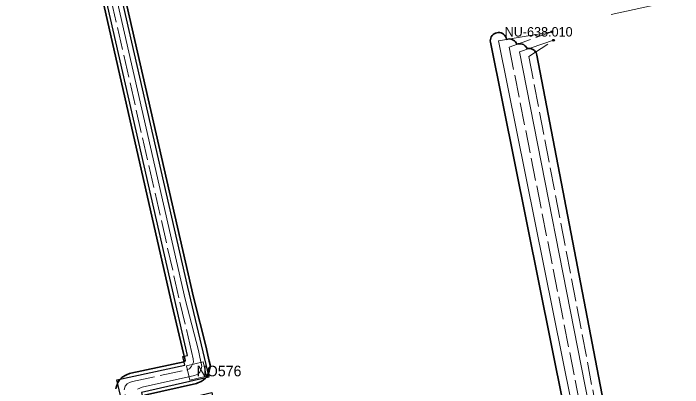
# Model space of a CAD drawing. Extents: x -452602 to -451136, y -1100088 to -1099653.
# Drawn here: x -451906 to -451849.1, y -1099931.7 to -1099899.9 of the extents above; entities that cross this region are included whole.
import ezdxf

# ---------------------------------------------------------------- set-up
doc = ezdxf.new("R2010")
doc.units = 0
doc.header["$LTSCALE"] = 0.32
doc.header["$PDMODE"] = 32
doc.header["$PDSIZE"] = 0.16
doc.linetypes.add('LONG_DASHED', pattern=[7.5, 6, -1.5])
for name, color, linetype, lineweight in [('2', 7, 'Continuous', 13), ('3', 7, 'Continuous', 25), ('8', 7, 'Continuous', 35)]:
    doc.layers.add(name, color=color, linetype=linetype, lineweight=lineweight)
doc.layers.add('4', color=7, linetype='Continuous')

msp = doc.modelspace()

# ---------------------------------------------------------------- linework, layer by layer
at = {"layer": '2'}
for p, q in [((-451864.778, -1099902.248), (-451860.254, -1099901.494)), ((-451864.778, -1099902.248), (-451858.58, -1099933.019)), ((-451862.992, -1099903.201), (-451860.093, -1099902.215)), ((-451862.992, -1099903.201), (-451857.038, -1099933.512))]:
    msp.add_line(p, q, dxfattribs=at)
at = {"layer": '2', "linetype": 'LONG_DASHED'}
for p, q in [((-451863.866, -1099902.804), (-451860.254, -1099901.494)), ((-451862.199, -1099903.597), (-451860.093, -1099902.215)), ((-451863.866, -1099902.804), (-451857.821, -1099933.303)), ((-451862.199, -1099903.597), (-451856.41, -1099933.788))]:
    msp.add_line(p, q, dxfattribs=at)
msp.add_lwpolyline([(-451884.148, -1099958.159), (-451889.562, -1099934.377), (-451889.84, -1099933.965), (-451890.149, -1099933.711), (-451890.612, -1099933.592), (-451895.202, -1099934.69), (-451895.566, -1099934.604), (-451895.804, -1099934.471), (-451896.029, -1099934.147), (-451896.558, -1099931.872), (-451896.466, -1099931.548), (-451896.3, -1099931.363), (-451896.115, -1099931.25), (-451895.85, -1099931.151), (-451891.253, -1099930.179), (-451891.022, -1099930.079), (-451890.85, -1099929.874), (-451890.685, -1099929.517), (-451890.697, -1099929.246), (-451890.836, -1099928.624), (-451891.909, -1099924.065), (-451905.286, -1099865.27)], dxfattribs=at)
at = {"layer": '2'}
for points in [[(-451895.434, -1099931.826), (-451895.043, -1099931.654), (-451890.579, -1099930.648), (-451890.307, -1099930.529), (-451890.122, -1099930.364), (-451890.016, -1099930.099), (-451889.957, -1099929.881), (-451890.016, -1099929.596), (-451890.135, -1099929.087), (-451890.261, -1099928.545), (-451891.367, -1099924.177), (-451904.853, -1099865.12)], [(-451855.216, -1099900.028), (-451818.069, -1099891.931), (-451811.719, -1099923.681)]]:
    msp.add_lwpolyline(points, dxfattribs=at)
at = {"layer": '3'}
msp.add_lwpolyline([(-451884.541, -1099958.233), (-451888.102, -1099942.592), (-451889.924, -1099934.589), (-451890.439, -1099934.698), (-451890.615, -1099934.004), (-451896.154, -1099935.38), (-451897.17, -1099931.022), (-451891.416, -1099929.782), (-451891.584, -1099929.042), (-451891.175, -1099928.947), (-451900.352, -1099888.829), (-451899.104, -1099888.498), (-451891.188, -1099923.166), (-451889.365, -1099930.782), (-451895.086, -1099932.109), (-451894.784, -1099933.414), (-451889.116, -1099932.088), (-451888.572, -1099934.622), (-451883.239, -1099957.987)], close=True, dxfattribs=at)
at = {"layer": '3', "lineweight": 13}
msp.add_lwpolyline([(-451891.255, -1099929.835), (-451889.861, -1099929.5), (-451889.577, -1099930.711), (-451890.972, -1099931.042)], close=True, dxfattribs=at)
at = {"layer": '4'}
for p in [(-451860.254, -1099901.494), (-451860.093, -1099902.215)]:
    msp.add_point(p, dxfattribs=at)
at = {"layer": '8'}
for points in [[(-451904.17, -1099864.964), (-451890.687, -1099924.013), (-451889.582, -1099928.373), (-451889.579, -1099928.387), (-451889.454, -1099928.929), (-451889.335, -1099929.437), (-451889.332, -1099929.451), (-451889.272, -1099929.738), (-451889.258, -1099929.847), (-451889.261, -1099929.957), (-451889.281, -1099930.065), (-451889.341, -1099930.283), (-451889.352, -1099930.319), (-451889.366, -1099930.359), (-451889.472, -1099930.624), (-451889.52, -1099930.72), (-451889.581, -1099930.808), (-451889.656, -1099930.886), (-451889.841, -1099931.051), (-451889.929, -1099931.118), (-451890.026, -1099931.17), (-451890.297, -1099931.289), (-451890.425, -1099931.331), (-451894.823, -1099932.322)], [(-451897.254, -1099931.796), (-451897.231, -1099931.68), (-451897.139, -1099931.355), (-451897.102, -1099931.257), (-451897.052, -1099931.165), (-451896.988, -1099931.081), (-451896.822, -1099930.896), (-451896.748, -1099930.824), (-451896.663, -1099930.764), (-451896.478, -1099930.652), (-451896.421, -1099930.621), (-451896.361, -1099930.595), (-451896.096, -1099930.496), (-451895.995, -1099930.466), (-451891.466, -1099929.508), (-451891.451, -1099929.502), (-451891.446, -1099929.496), (-451891.392, -1099929.379), (-451891.394, -1099929.34), (-451891.519, -1099928.781), (-451892.591, -1099924.223), (-451905.967, -1099865.43)], [(-451859.266, -1099933.158), (-451865.465, -1099902.386), (-451865.477, -1099902.265), (-451865.469, -1099902.144), (-451865.439, -1099902.027), (-451865.39, -1099901.916), (-451865.323, -1099901.815), (-451865.239, -1099901.727), (-451865.141, -1099901.655), (-451865.032, -1099901.602), (-451864.916, -1099901.567), (-451864.795, -1099901.554), (-451864.674, -1099901.561), (-451864.556, -1099901.589), (-451864.444, -1099901.638), (-451864.343, -1099901.705), (-451864.255, -1099901.788), (-451864.182, -1099901.885), (-451864.127, -1099901.994), (-451864.092, -1099902.11), (-451864.088, -1099902.132), (-451863.973, -1099902.104), (-451863.856, -1099902.096), (-451863.739, -1099902.108), (-451863.626, -1099902.139), (-451863.52, -1099902.189), (-451863.423, -1099902.256), (-451863.339, -1099902.337), (-451863.269, -1099902.432), (-451863.217, -1099902.537), (-451863.105, -1099902.51), (-451862.991, -1099902.501), (-451862.877, -1099902.51), (-451862.766, -1099902.538), (-451862.66, -1099902.584), (-451862.564, -1099902.647), (-451862.48, -1099902.724), (-451862.409, -1099902.814), (-451862.353, -1099902.915), (-451862.242, -1099902.899), (-451862.13, -1099902.901), (-451862.02, -1099902.921), (-451861.914, -1099902.958), (-451861.815, -1099903.012), (-451861.727, -1099903.08), (-451861.65, -1099903.162), (-451861.588, -1099903.256), (-451861.541, -1099903.357), (-451861.511, -1099903.466), (-451855.722, -1099933.656)]]:
    msp.add_lwpolyline(points, dxfattribs=at)

# ---------------------------------------------------------------- texts
at = {"layer": '3'}
msp.add_text('NO576 ', height=0.9, dxfattribs=at).set_placement((-451890.416, -1099930.721))
at = {"layer": '4'}
msp.add_text('NU-638.010', height=0.8, dxfattribs=at).set_placement((-451864.254, -1099901.894))

doc.saveas('drawing.dxf')
